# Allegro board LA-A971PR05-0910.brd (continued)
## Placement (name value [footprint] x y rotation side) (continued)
NOREF#24  -  []  129.2 19.65 0 top
NOREF#25  -  []  103 83.87 0 top
NOREF#26  -  []  103 61.73 0 top
NOREF#27  -  []  146.65 4.94 0 top
NOREF#28  -  []  227.2 108.55 180 bottom
NOREF#29  -  []  93.42 48.56 180 bottom
NOREF#30  -  []  40.82 35.98 180 bottom
NOREF#31  -  []  24.75 12.35 180 bottom
NOREF#32  -  []  24.34 8.13 180 bottom
PBATT1  LLTOP_ALLTOP C144LS-109A9-L 9P BATT P2  [ALLTO_C144LS-109A9-L_9P-T]  170.2 2.3 180 bottom
PC1  1U_0603_10V4Z  [C_0603]  225.71 96.8 270 top
PC3  2200P_0402_50V7K~D  [C_0402]  173.28 7.48 270 top
PC4  1500P_0402_50V7K  [C_0402]  157.02 7.86 270 top
PC5  0.022U_0805_50V7K  [C_0805]  81.75 84.43 0 top
PC9  1000P_0603_50V7K  [C_0603]  93.27 90.72 0 top
PC10  10U_0805_25V6K  [C_0805]  81.08 73.91 270 top
PC11  0.1U_0603_25V7K  [C_0603]  81.78 82.46 270 top
PC100  4.7U_0603_10V6K  [C_0603]  200.46 44.87 90 top
PC101  10U_0805_25V6K  [C_0805]  200.71 55.77 90 top
PC102  10U_0805_25V6K  [C_0805]  202.44 55.77 90 top
PC105  2200P_0402_50V7K  [C_0402]  203.73 56.48 90 top
PC106  0.1U_0402_25V6  [C_0402]  204.61 56.49 90 top
PC109  0.1U_0603_25V7K  [C_0603]  205.47 50.13 90 top
PC110  0.1U_0603_25V7K  [C_0603]  195.49 49.83 0 top
PC111  680P_0603_50V7K  [C_0603]  204.46 63.6 180 top
PC113  150U_D_6.3VM_R15M  [C_V]  211.89 62.08 90 bottom
PC114  680P_0603_50V7K  [C_0603]  200.46 63.41 0 top
PC115  150U_D_6.3VM_R15M  [C_V]  196.58 68.24 0 bottom
PC117  0.1U_0603_25V7K  [C_0603]  201.41 53.44 0 top
PC118  4.7U_0603_10V6K  [C_0603]  200.27 53.44 180 top
PC119  1U_0603_10V6K  [C_0603]  196.82 47.54 180 top
PC200  10U_0805_25V6K  [C_0805]  192.68 7.82 0 top
PC201  10U_0805_25V6K  [C_0805]  192.68 9.54 0 top
PC203  2200P_0402_50V7K  [C_0402]  193.61 6.49 0 top
PC204  0.22U_0603_16V7K  [C_0603]  190.87 9.05 180 top
PC205  22U_0805_6.3V6M  [C_0805]  182.74 6.83 180 top
PC206  0.1U_0402_25V6  [C_0402]  192.77 6.49 180 top
PC207  220U_D2_2VY_R17M  [C_D2]  204.33 13.14 270 bottom
PC208  680P_0603_50V7K  [C_0603]  201.47 7.91 180 top
PC209  1U_0603_10V6K  [C_0603]  190.88 5.44 180 top
PC211  1U_0603_10V6K  [C_0603]  189.48 2.97 0 top
PC212  0.033U_0402_16V7K  [C_0402]  183.19 5.5 180 top
PC213  100P_0402_50V8J  [C_0402]  182.74 3.7 90 top
PC214  .1U_0402_16V7K  [C_0402]  180.96 4.61 180 top
PC215  .1U_0402_16V7K  [C_0402]  186.4 3.29 270 top
PC300  2200P_0402_50V7K  [C_0402]  192.76 58.9 0 bottom
PC301  680P_0603_50V7K  [C_0603]  191.5 61.89 270 top
PC302  0.1U_0603_25V7K  [C_0603]  189.6 58.14 0 top
PC303  10U_0805_25V6K  [C_0805]  193.28 59.96 90 bottom
PC304  330P_0402_50V7K  [C_0402]  187.31 57.7 180 bottom
PC305  47U_0805_6.3V6M  [C_0805]  187.61 69.63 180 top
PC306  47U_0805_6.3V6M  [C_0805]  187.61 67.91 180 top
PC307  22U_0805_6.3VAM  [C_0805]  187.54 65.01 180 bottom
PC308  22U_0805_6.3VAM  [C_0805]  187.54 66.72 180 bottom
PC309  4.7U_0603_6.3V6K  [C_0603]  187.44 57.82 180 top
PC310  4.7U_0603_6.3V6K  [C_0603]  188.86 56.68 0 bottom
PC311  0.1U_0402_25V6  [C_0402]  190.32 57.72 180 bottom
PC400  1U_0402_6.3V6K  [C_0402]  95.01 95.47 180 bottom
PC401  4.7U_0805_6.3V6K  [C_0805]  95.72 92.75 0 bottom
PC402  .1U_0402_16V7K  [C_0402]  94.09 97.31 90 bottom
PC403  0.01U_0402_25V7K  [C_0402]  104.27 95.33 90 bottom
PC404  22U_0805_6.3V6M  [C_0805]  100.28 92.75 180 bottom
PC500  4700P_0603_50V7K  [C_0603]  90.09 68.36 90 top
PC501  .1U_0402_16V7K  [C_0402]  91.17 69.82 270 top
PC502  0.068U_0402_16V7K  [C_0402]  94.55 71.86 180 top
PC503  1000P_0402_50V7K  [C_0402]  77.81 66.38 0 bottom
PC504  0.1U_0402_25V6  [C_0402]  77.89 68.94 0 bottom
PC505  1U_0603_10V6K  [C_0603]  84.3 76.63 0 top
PC506  100P_0402_50V8J  [C_0402]  94.54 76.63 180 top
PC507  0.33U_0603_10V7K  [C_0603]  90.98 74.9 90 bottom
PC508  680P_0603_50V7K  [C_0603]  82.59 60.69 90 bottom
PC509  1U_0603_10V7K  [C_0603]  87.17 67.6 180 bottom
PC510  1U_0603_10V7K  [C_0603]  89.78 74.9 90 bottom
PC511  0.1U_0402_25V6  [C_0402]  86.14 80.56 0 top
PC512  1500P_0402_50V7K  [C_0402]  93.64 79.31 270 top
PC513  0.068U_0402_16V7K  [C_0402]  94.55 70.9 180 top
PC514  47P_0402_50V8J  [C_0402]  88.4 79.73 0 top
PC515  10U_0805_25V6K  [C_0805]  79.15 62.9 0 top
PC516  10U_0805_25V6K  [C_0805]  79.15 62.9 0 bottom
PC517  10U_0805_25V6K  [C_0805]  79.15 61.12 0 bottom
PC518  10U_0805_25V6K  [C_0805]  79.15 61.12 0 top
PC519  100U_D_20VM_R55M  [C_D]  80.55 57.58 0 bottom
PC520  2200P_0402_50V7K  [C_0402]  79.16 64.24 0 top
PC521  0.1U_0402_25V6  [C_0402]  79.17 65.13 0 top
PC700  0.1U_0603_25V7K  [C_0603]  48.44 24.36 270 top
PC701  1U_0603_25V6K  [C_0603]  53.2 9.37 90 bottom
PC702  0.1U_0402_25V6  [C_0402]  52.69 12.1 0 top
PC703  0.1U_0402_25V6  [C_0402]  54.23 10.45 270 bottom
PC704  10U_0805_25V6K  [C_0805]  81.09 12.96 90 top
PC705  10U_0805_25V6K  [C_0805]  77.53 12.96 90 top
PC706  10U_0805_25V6K  [C_0805]  79.35 12.96 90 bottom
PC707  10U_0805_25V6K  [C_0805]  77.53 12.96 90 bottom
PC708  22U_0805_25V6M  [C_0805]  81.09 12.96 90 bottom
PC709  10U_0805_25V6K  [C_0805]  54.95 12.15 0 top
PC710  1U_0603_10V6K  [C_0603]  57.01 7.09 0 top
PC711  0.1U_0402_25V6  [C_0402]  52.13 10.64 270 bottom
PC712  0.047U_0603_25V7K~D  [C_0603]  57.29 10.64 180 top
PC713  2200P_0402_50V7K  [C_0402]  61.4 14.74 0 bottom
PC714  22U_0805_25V6M  [C_0805]  59.22 10.62 0 top
PC715  22U_0805_25V6M  [C_0805]  60.68 14.83 0 top
PC716  22U_0805_25V6M  [C_0805]  59.08 10.39 0 bottom
PC717  22U_0805_25V6M  [C_0805]  60.69 13.09 0 top
PC718  100P_0402_50V8J  [C_0402]  50.36 9.72 90 bottom
PC719  100P_0402_50V8J  [C_0402]  51.18 8.71 180 bottom
PC721  1000P_0603_50V7K  [C_0603]  69.18 11.23 270 top
PC722  0.1U_0603_25V7K  [C_0603]  82.87 13.11 90 top
PC723  10U_0805_25V6K  [C_0805]  84.58 12.96 90 top
PC724  10U_0805_25V6K  [C_0805]  82.87 12.96 90 bottom
PC725  10U_0805_25V6K  [C_0805]  84.58 12.96 90 bottom
PC726  0.1U_0402_25V6  [C_0402]  52.88 6.69 270 bottom
PC727  0.1U_0402_25V6  [C_0402]  53.87 4.32 180 top
PC728  0.1U_0402_25V6  [C_0402]  51.99 5.78 90 bottom
PC729  1U_0603_25V6K  [C_0603]  55.22 5.93 180 bottom
PC732  0.1U_0402_25V6  [C_0402]  61.4 13.83 0 bottom
PC737  100P_0402_50V8J  [C_0402]  46.79 7.32 90 top
PC741  100P_0402_50V8J  [C_0402]  47.67 5.51 90 top
PC805  0.1U_0402_10V7K  [C_0402]  30.85 7.2 90 top
PC807  0.47U_0805_25V6K  [C_0805]  107.3 12.06 270 bottom
PC809  1500P_0402_50V7K  [C_0402]  17.82 40.51 0 top
PC810  0.1U_0402_10V7K  [C_0402]  15.51 38.91 0 top
PC813  0.1U_0603_50V4Z  [C_0603]  23.35 22.88 180 top
PC815  0.1U_0603_25V7K  [C_0603]  23.35 21.61 180 top
PC816  0.047U_0603_25V7M  [C_0603]  26.12 15.64 270 top
PC817  0.1U_0402_25V4Z~D  [C_0402]  27.15 15.67 270 top
PC900  22U_0805_6.3V6M  [C_0805]  106.14 66.44 90 bottom
PC901  22U_0805_6.3V6M  [C_0805]  104.4 66.44 90 bottom
PC902  22U_0805_6.3V6M  [C_0805]  102.68 66.45 90 bottom
PC903  22U_0805_6.3V6M  [C_0805]  106.11 69.81 90 bottom
PC904  22U_0805_6.3V6M  [C_0805]  104.4 69.81 90 bottom
PC913  22U_0805_6.3V6M  [C_0805]  105.98 73.14 90 bottom
PC914  22U_0805_6.3V6M  [C_0805]  104.24 73.13 90 bottom
PC915  2.2U_0805_10V6K  [C_0805]  102.68 69.81 90 bottom
PC916  2.2U_0805_10V6K  [C_0805]  100.95 66.45 90 bottom
PC917  22U_0805_6.3V6M  [C_0805]  102.51 73.13 90 bottom
PC966  220U 2.5V Y D2 ESR9M H1.9 SX  [C_D2]  96.55 82 90 bottom
PD1  -  [TVNST52302AB0_SOT523-3]  166.87 6.58 180 top
PD2  -  [TVNST52302AB0_SOT523-3]  164.83 7.98 0 top
PD3  BAS40CW SOT-323  [BAS40-05W_SC70-3]  226.82 96.11 90 top
PD4  SDMK0340L-7-F_SOD323-2~D  [RB751V-40_SOD323-2]  162.99 8.85 270 top
PD5  -  [AZC199-02SPR7G_SOT23-3]  75.9 95.69 180 top
PD702  SDMK0340L-7-F_SOD323-2~D  [SDMK0340L-7-F_SOD323-2]  59.61 4.99 180 bottom
PD704  SDMK0340L-7-F_SOD323-2~D  [SDMK0340L-7-F_SOD323-2]  102.89 7.35 180 bottom
PD705  SDMK0340L-7-F_SOD323-2~D  [SDMK0340L-7-F_SOD323-2]  102.89 9.09 180 bottom
PD800  -  [PDS5100H-13_POWERDI5-3]  87.44 7.25 0 bottom
PD808  -  [PDS5100H-13_POWERDI5-3]  105.32 9.37 180 top
PD813  SDMK0340L-7-F_SOD323-2~D  [SDMK0340L-7-F_SOD323-2]  23.04 38.77 270 top
PD815  -  [BAT54CW_SOT323-3]  35.75 20.57 180 top
PD817  -  [BAT54CW_SOT323-3]  26.02 35.5 90 top
PH500  100K_0402_1%_NCP15WF104F03RC  [R_0402]  84.52 69.63 180 bottom
PH501  10K_0402_1%_TSM0A103F34D1RZ  [R_0402]  92.48 66.15 0 top
PJP1  PAD-OPEN 1x3m  [JUMP_43X118]  91.58 81.51 0 bottom
PJP6  PAD-OPEN1x2m  [JUMP_43X79]  254.28 44.87 180 top
PJP9  PAD-OPEN1X2m  [JUMP_43X79]  251.6 26.31 90 top
PJP10  PAD-OPEN1x1m  [JUMP_43X39]  254.61 25.47 90 top
PJP11  PAD-OPEN1x1m  [JUMP_43X39]  193.85 52.95 270 top
PJP12  PAD-OPEN1x1m  [JUMP_43X39]  197.47 43.17 270 top
PJP13  PAD-OPEN1x1m  [JUMP_43X39]  209.28 49.45 270 bottom
PJP14  PAD-OPEN1x1m  [JUMP_43X39]  237.61 49.73 180 top
PJP15  PAD-OPEN1x1m  [JUMP_43X39]  252.84 59.93 180 top
PJP16  PAD-OPEN1x1m  [JUMP_43X39]  214.16 14.01 180 top
PJP19  PAD-OPEN1x1m  [JUMP_43X39]  45.39 29.96 270 top
PJP20  PAD-OPEN1x1m  [JUMP_43X39]  45.45 23.8 270 top
PJP21  PAD-OPEN1x3m  [JUMP_43X118]  208.29 75.59 270 top
PJP22  PAD-OPEN1x3m  [JUMP_43X118]  210.38 66.71 0 top
PJP23  PAD-OPEN1x1m  [JUMP_43X39]  132.89 90.03 270 top
PJP24  PAD-OPEN1x1m  [JUMP_43X39]  209.81 83.5 90 bottom
PJP25  PAD-OPEN1x1m  [JUMP_43X39]  209.87 78.51 270 bottom
PJP26  PAD-OPEN1x1m  [JUMP_43X39]  253.21 11.28 0 top
PJP27  PAD-OPEN1x1m  [JUMP_43X39]  207.63 78.41 270 bottom
PJP28  PAD-OPEN1x1m  [JUMP_43X39]  207.59 84.42 270 bottom
PJP29  PAD-OPEN1x1m  [JUMP_43X39]  179.57 55.97 90 top
PJP32  PAD-OPEN1x1m  [JUMP_43X39]  211.06 42.57 90 bottom
PJP36  PAD-OPEN1x1m  [JUMP_43X39]  147.04 91.49 180 top
PJP41  PAD-OPEN1x1m  [JUMP_43X39]  211.51 49.45 270 bottom
PJP42  PAD-OPEN1x1m  [JUMP_43X39]  213.28 42.57 90 bottom
PJP51  PAD-OPEN1x1m  [JUMP_43X39]  146.1 89.26 0 top
PJP100  PAD-OPEN 1x3m  [JUMP_43X118]  211.23 53.53 90 bottom
PJP101  PAD-OPEN 1x3m  [JUMP_43X118]  199.44 67.12 90 top
PJP102  PAD-OPEN 1x3m  [JUMP_43X118]  206.93 67.31 90 bottom
PJP200  PAD-OPEN 1x2m~D  [JUMP_43X79]  193.79 4.04 180 top
PJP201  PAD-OPEN1x1m  [JUMP_43X39]  189.85 12.93 0 top
PJP202  PAD-OPEN1x1m  [JUMP_43X39]  182.37 8.8 180 top
PJP203  JUMP_1x3m  [JUMP_43X118]  199.83 13.89 90 top
PJP204  JUMP_1x3m  [JUMP_43X118]  202.8 18.95 180 top
PJP300  PAD-OPEN 1x2m~D  [JUMP_43X79]  186.23 62.75 270 bottom
PJP302  PAD-OPEN 1x2m~D  [JUMP_43X79]  192.65 56.19 90 bottom
PJP400  PAD-OPEN1x1m  [JUMP_43X39]  94.03 92.95 90 bottom
PJP401  PAD-OPEN1x1m  [JUMP_43X39]  101.57 92.49 0 bottom
PJP500  PAD-OPEN 4x4m  [JUMP_43X118]  74.81 57.38 0 bottom
PJP700  PAD-OPEN 1x2m~D  [JUMP_43X79-NPM]  57.68 13.75 0 bottom
PJP701  PAD-OPEN1x1m  [JUMP_43X39]  54.47 8.17 270 bottom
PJPDC1  ACES_50299-0050N-001  [ACES_50299-0050N-001_5P]  91.35 92.8 270 bottom
PL1  FBMJ4516HS720NT_2P~D  [TAIYO_FBMJ4516HS720NT_2P]  169.02 7.08 90 top
PL2  FBMJ4516HS720NT_2P~D  [TAIYO_FBMJ4516HS720NT_2P]  171.31 7.08 90 top
PL3  BLM15AG102SN1D_2P  [MURAT_BLM15AG102SN1D_2P]  75.81 91.87 180 top
PL4  FBMJ4516HS720NT_2P  [TAIYO_FBMJ4516HS720NT_2P]  86.29 81.7 180 bottom
PL100  1UH +-20% 6.6A  [L_5X5X3_M_2P-NPM]  211.23 52.03 90 bottom
PL101  2.2UH_7.8A_20%  [PANAS_ETQP3W2R2WFN_2P]  205.6 63.9 90 bottom
PL102  3.3UH_6.3A_20%  [PANAS_ETQP3W2R2WFN_2P]  198.11 57.91 270 bottom
PL200  1UH_11A_20%  [PANAS_ETQP3W2R2WFN_2P]  200.05 10.39 0 bottom
PL301  0.68UH +-20% 7.9A  [L_5X5X3_M_2P]  191.76 64.73 90 bottom
PL500  0.15UH_PCME064T-R15MS0R667_36A_20%  [PANAS_ETQP4LR15AFM_4P]  96.42 62.66 180 bottom
PL501  FBMA-L11-453215800LMA90T_2P  [KC_FBMA-L1_2P-NPM]  73.46 57.38 0 bottom
PL700  1UH_PCMB042T-1R0MS_4.5A_20%  [CYNTE_PCMB042T-1R0MS_2P]  60.02 13.5 180 bottom
PL701  3.3UH +-20% PIMB104T 10A  [TOKO_FDVE1040-H-3R3M-P3_2P]  73.78 10.43 180 bottom
PQ1  -  [DMG2301U-7_SOT23-3]  160.86 8.04 90 top
PQ2  -  [FDV301N-G_SOT23-3]  78.18 87.86 90 top
PQ3  MMST3904-7-F_SOT323~D  [MMST3904-7-F_SOT323-3]  72.44 87.16 90 top
PQ4  -  [FDMC6679AZ_MLP8-5]  82.07 79.99 0 bottom
PQ6  DCX124EK-7-F PNP/NPN_SC74-6~D  [IMD2AT-108_SC74-6]  82.99 87.98 90 top
PQ100  -  [SIS412DN-T1-GE3_POWERPAK8-5]  208.05 58.18 180 top
PQ101  -  [SIS412DN-T1-GE3_POWERPAK8-5]  198.91 58.24 180 top
PQ102  -  [SI7716ADN-T1-GE3_POWERPAK8-5]  203.97 61.99 270 top
PQ103  -  [SI7716ADN-T1-GE3_POWERPAK8-5]  201 59.75 90 top
PQ200  -  [SIS412DN-T1-GE3_POWERPAK8-5]  195.1 11.3 90 top
PQ201  -  [SI7716ADN-T1-GE3_POWERPAK8-5]  196.61 8.95 0 top
PQ700  V30415-T1-GE3 1P POWERPAK1212-8  [SI7121DN-T1-GE3_POWERPAK8-5]  80.78 73.72 90 bottom
PQ701  -  [NTR4502PT1G_SOT23-3]  49.82 17.26 270 top
PQ702  -  [NTR4502PT1G_SOT23-3]  49.82 21.26 270 top
PQ703  SI3993CDV-T1-GE3_TSOP6  [NTGD4161PT1G_TSOP6]  54.18 19.72 270 top
PQ704  -  [AON6970_DFN5X6D-8-7]  61.35 8.61 270 top
PQ712  -  [DMN65D8LW-7_SOT323-3]  22.28 29.6 90 top
PQ800  -  [SI4835DDY-T1-GE3_SO8]  86.63 10.3 90 bottom
PQ806  -  [DMN65D8LDW-7_SOT363-6]  34.17 11.57 180 top
PQ810  -  [FDS6679AZ-G_SO8]  104.77 14.52 270 bottom
PQ813  -  [DMN65D8LDW-7_SOT363-6]  27.53 29.53 0 top
PQ814  -  [NTR4502PT1G_SOT23-3]  22.21 33.2 270 top
PQ815  -  [FDS6679AZ-G_SO8]  93.78 11.03 0 bottom
PQ816  -  [DMN65D8LW-7_SOT323-3]  18.92 36.99 90 top
PQ817  -  [DMN65D8LDW-7_SOT363-6]  12.2 36.19 0 top
PQ826  -  [FDMC6679AZ_MLP8-5]  94.92 12.91 90 bottom
PQ829  DMG2301U-7 1P SOT23-3  [SI2301CDS-T1-GE3_SOT23-3]  35.55 24.97 0 top
PQ832  -  [DMN65D8LW-7_SOT323-3]  33.39 29.69 90 top
PR1  1K_0402_5%  [R_0402]  229.64 96.62 270 top
PR2  100K_0402_5%  [R_0402]  162.6 10.13 0 top
PR6  0_0402_5%  [R0402_0OHM]  157.02 9.64 270 top
PR7  0_0402_5%  [R_0402]  76.07 84.49 180 top
PR8  2.2K_0402_5%  [R_0402]  74.22 84.51 270 top
PR9  33_0402_5%  [R_0402]  75.18 85.4 180 top
PR10  100K_0402_1%  [R_0402]  75.16 83.6 0 top
PR11  10K_0402_1%  [R_0402]  73.52 86.96 90 top
PR12  15K_0402_1%  [R_0402]  69.89 84.81 0 top
PR13  10K_0402_5%  [R_0402]  74.41 87.87 270 top
PR14  1M_0402_5%  [R_0402]  80.7 82.07 90 top
PR15  100K_0402_5%  [R_0402]  82.41 73.52 270 top
PR16  4.7K_0805_5%  [R_0805]  83.3 82.55 270 top
PR17  10K_0402_5%  [R_0402]  80.26 84.75 180 top
PR18  1M_0402_5%  [R_0402]  80.26 83.86 180 top
PR100  6.49K_0402_1%  [R_0402]  202.48 45.44 90 top
PR101  15K_0402_1%  [R_0402]  199.43 46.35 270 top
PR102  10K_0402_1%  [R_0402]  203.36 45.44 90 top
PR103  0_0402_5%  [R0402_0OHM]  201.54 45.43 90 top
PR104  10K_0402_1%  [R_0402]  198.54 46.35 270 top
PR105  20K_0402_1%  [R_0402]  204.25 45.44 90 top
PR106  16.9K_0402_1%  [R_0402]  197.65 45.44 90 top
PR107  100K_0402_1%  [R_0402]  205.16 48.69 270 top
PR108  0_0402_5%  [R0402_0OHM]  204.25 47.78 90 top
PR109  2.2_0603_5%  [R_0603]  196.89 51.1 180 top
PR110  2.2_0603_5%  [R_0603]  205.71 52.62 180 top
PR111  4.7_1206_5%  [R_1206]  208.33 63.86 180 top
PR112  4.7_1206_5%  [R_1206]  196.58 63.66 0 top
PR113  0_0402_5%  [R0402_0OHM]  195.68 46.46 0 top
PR114  200_0402_1%  [R_0402]  196.58 48.69 180 top
PR200  2.2_0603_5%  [R_0603]  189.85 10.39 180 top
PR201  19.6K_0402_1%  [R_0402]  190.42 6.51 180 top
PR202  5.1_0603_5%  [R_0603]  188.34 2.31 90 top
PR203  4.7_1206_5%  [R_1206]  200.39 11.85 270 top
PR204  0_0603_5%  [R_0603]  189.48 4.21 0 top
PR205  8.06K_0402_1%  [R_0402]  181.85 3.7 90 top
PR206  768K_0402_1%  [R_0402]  187.29 2.37 90 top
PR207  0_0402_5%  [R0402_0OHM]  185.47 2.37 90 top
PR209  10K_0402_1%  [R_0402]  180.98 3.72 180 top
PR210  0_0402_5%  [R0402_0OHM]  184.58 2.37 90 top
PR303  1M_0402_1%  [R_0402]  187.39 59.08 180 bottom
PR305  4.7_1206_5%  [R_1206]  188.96 63.35 0 top
PR306  0_0402_5%  [R_0402]  186.54 59.09 0 top
PR307  7.5K_0402_1%  [R_0402]  187.31 56.81 180 bottom
PR308  0_0402_5%  [R_0402]  187.45 59.98 180 top
PR309  1K_0402_5%  [R_0402]  185.52 57.71 270 bottom
PR310  10K_0402_1%  [R_0402]  186.63 55.94 180 bottom
PR312  0_0603_5%  [R_0603]  190.23 59.22 90 top
PR313  0_0402_5%  [R0402_0OHM]  186.16 61.81 0 top
PR315  100K_0402_1%  [R_0402]  186.16 60.92 0 top
PR400  100K_0402_5%  [R_0402]  94.1 96.42 0 bottom
PR401  47K_0402_5%  [R_0402]  94.98 97.31 90 bottom
PR402  8.66K_0402_1%  [R_0402]  103.38 95.33 90 bottom
PR403  10K_0402_1%  [R_0402]  103.38 97.17 90 bottom
PR500  75_0402_1%  [R_0402]  92.06 69.82 270 top
PR501  316K_0402_1%  [R_0402]  89.01 68.91 90 top
PR502  75_0402_1%  [R_0402]  88.06 69.82 270 top
PR503  681K_0402_1%  [R_0402]  87.17 69.82 270 top
PR504  36.5K_0402_1%  [R_0402]  86.28 69.82 270 top
PR505  10K_0402_5%  [R_0402]  90.59 72.57 270 bottom
PR506  39K_0402_1%  [R_0402]  89.7 72.57 270 bottom
PR507  150K_0402_1%  [R_0402]  88.81 72.57 270 bottom
PR508  100K_0402_1%  [R_0402]  87.92 72.57 270 bottom
PR509  20K_0402_1%  [R_0402]  87.03 72.57 270 bottom
PR510  39K_0402_5%~N  [R_0402]  91.48 72.57 270 bottom
PR511  10K_0402_5%  [R_0402]  92.95 68.87 90 top
PR512  2.15K_0402_1%  [R_0402]  91.6 65.27 270 top
PR513  75_0402_1%  [R_0402]  85.14 72.56 180 top
PR514  20K_0402_1%  [R_0402]  92.49 65.27 270 top
PR515  3.01K_0402_1%  [R_0402]  93.38 65.27 270 top
PR516  1.91K_0402_1%  [R_0402]  85.14 74.34 180 top
PR517  2.2_0603_5%  [R_0603]  79.03 67.8 180 bottom
PR518  2M_0402_1%  [R_0402]  89.05 69.1 0 bottom
PR519  1_0603_5%  [R_0603]  84.3 75.42 0 top
PR520  0_0402_5%  [R0402_0OHM]  84.23 71.67 0 top
PR521  4.22K_0402_1%  [R_0402]  92.68 77.63 90 top
PR522  4.7_1206_5%  [R_1206]  84.24 63.35 270 bottom
PR523  10K_0402_5%  [R_0402]  94.54 77.52 180 top
PR524  2M_0402_1%  [R_0402]  89.97 69.98 180 bottom
PR525  27K_0402_1%  [R_0402]  89.97 68.21 180 bottom
PR526  10_0603_1%  [R_0603]  90.22 78.84 0 top
PR527  54.9_0402_1%  [R_0402]  87.05 79.68 270 top
PR528  75_0402_1%  [R_0402]  86.16 79.68 270 top
PR529  110_0402_1%  [R_0402]  85.03 78.02 180 top
PR531  0_0402_5%  [R0402_0OHM]  94.54 75.61 180 top
PR532  0_0402_5%  [R0402_0OHM]  94.54 74.72 180 top
PR534  0_0402_5%  [R0402_0OHM]  89 78.86 270 top
PR535  4.75K_0402_1%  [R_0402]  94.53 78.39 90 top
PR536  0_0402_5%  [R0402_0OHM]  84.23 70.78 0 top
PR539  0_0402_5%  [R0402_0OHM]  85.14 73.45 180 top
PR700  0_0402_5%  [R0402_0OHM]  79.57 75.73 180 bottom
PR701  0.01_1206_1%  [R_1206_4P-D]  54.83 14.41 180 bottom
PR702  0_0402_5%  [R0402_0OHM]  47.36 24.12 270 top
PR703  100_0402_1%  [R_0402]  53.95 14.85 180 top
PR704  0_0402_5%  [R0402_0OHM]  53.06 13.06 90 top
PR705  0_0402_5%  [R0402_0OHM]  53.95 13.06 90 top
PR706  100K_0402_1%  [R_0402]  52.12 23.77 90 top
PR707  100K_0402_1%  [R_0402]  50.33 23.79 0 top
PR708  10_1206_5%  [R_1206]  57.35 7.97 90 bottom
PR709  0_0402_5%  [R0402_0OHM]  50.33 24.68 0 top
PR710  34K_0402_1%  [R_0402]  51.55 12.78 270 top
PR711  6.49K_0402_1%  [R_0402]  51.25 10.64 270 bottom
PR712  2.2_0603_5%  [R_0603]  57.14 8.17 90 top
PR713  100K_0402_1%  [R_0402]  48.57 3.52 90 top
PR714  0_0402_5%  [R0402_0OHM]  50.67 12.8 270 top
PR715  154K_0402_1%  [R_0402]  49.9 5.78 90 bottom
PR716  0_0402_5%  [R0402_0OHM]  49.79 12.8 270 top
PR717  0_0402_5%  [R0402_0OHM]  47.42 9.6 0 top
PR718  0_0402_5%  [R0402_0OHM]  47.42 11.38 0 top
PR720  0_0402_5%  [R0402_0OHM]  47.42 10.49 0 top
PR721  0.01_1206_1%  [R_1206_4P-D]  83.26 11.21 180 bottom
PR722  4.02K_0402_1%  [R_0402]  52.11 4.39 270 top
PR723  10_0603_1%  [R_0603]  54.18 4.71 0 bottom
PR725  1K_0402_1%  [R_0402]  51.23 3.49 90 top
PR726  4.7_1206_5%  [R_1206]  67.88 10.65 180 top
PR728  0_0402_5%  [R0402_0OHM]  49.44 4.33 0 top
PR729  154K_0402_1%  [R_0402]  50.79 5.78 90 bottom
PR737  649K_0402_1%  [R_0402]  45.91 8.23 270 top
PR738  3M_0402_5%  [R_0402]  48.59 7.24 270 top
PR740  10K_0402_1%  [R_0402]  46.78 6.42 270 top
PR743  0_0402_5%  [R0402_0OHM]  45.84 6.45 270 top
PR745  100K_0402_1%  [R_0402]  47.68 7.32 90 top
PR788  20K_0402_1%  [R_0402]  51.18 7.82 180 bottom
PR799  10K_0402_1%  [R_0402]  56.05 4.44 90 top
PR810  100K_0402_5%  [R_0402]  29.36 11.53 270 top
PR811  0_0402_5%  [R0402_0OHM]  106.85 9.31 0 bottom
PR812  0_0402_5%  [R0402_0OHM]  30.02 9.17 0 top
PR813  100K_0402_5%  [R_0402]  27.98 7.85 270 top
PR814  330K_0402_5%  [R_0402]  28.38 27.98 180 top
PR815  100K_0402_5%  [R_0402]  27.05 7.85 270 top
PR816  0_0402_5%  [R_0402]  26.14 7.85 270 top
PR818  100K_0402_5%  [R_0402]  18.73 39.62 180 top
PR819  100K_0402_5%  [R_0402]  12.2 39.17 0 top
PR822  10K_0402_5%  [R_0402]  19.66 39.64 270 top
PR826  100K_0402_5%  [R_0402]  26.08 32.73 0 top
PR827  100K_0402_5%  [R_0402]  26.08 33.62 0 top
PR828  10K_0402_5%  [R_0402]  35.5 31.47 180 top
PR829  100K_0402_5%  [R_0402]  29.9 30.78 270 top
PR830  100K_0402_5%  [R_0402]  33.01 27.77 90 top
PR831  100_0603_1%  [R_0603]  26.15 27.05 270 top
PR832  100_0603_1%  [R_0603]  27.36 25.65 90 top
PR835  47_0805_5%~D  [R_0805]  21.62 24.49 0 top
PR838  100_0603_1%  [R_0603]  30.38 25.48 90 top
PR842  0_0402_5%  [R0402_0OHM]  22.51 20.56 0 top
PR843  0_0402_5%  [R0402_0OHM]  33.18 23.65 0 top
PR844  10K_0402_5%  [R_0402]  36.13 19.6 180 top
PR845  0_0402_5%  [R0402_0OHM]  33.18 22.76 0 top
PR846  100K_0402_5%  [R_0402]  20.74 20.57 0 top
PR847  100_0603_1%  [R_0603]  21.98 19.52 0 top
PR848  0_0402_5%  [R0402_0OHM]  33.18 21.17 0 top
PR850  0_0402_5%  [R0402_0OHM]  33.18 19.39 0 top
PR851  0_0402_5%  [R0402_0OHM]  22.51 18.48 0 top
PR853  0_0402_5%  [R0402_0OHM]  28.77 33.62 180 top
PR854  0_0402_5%  [R0402_0OHM]  33.2 18.44 0 top
PR855  0_0402_5%  [R0402_0OHM]  22.51 17.55 0 top
PR857  0_0402_5%  [R0402_0OHM]  30.16 15.66 270 top
PR858  1M_0402_5%  [R_0402]  34.09 20.28 180 top
PR859  0_0402_5%  [R0402_0OHM]  31.03 15.66 270 top
PR860  100_0603_1%  [R_0603]  28.23 15.66 270 top
PR863  0_0402_5%  [R_0402]  33.2 17.49 0 top
PR864  100K_0402_5%  [R_0402]  22.42 16.67 180 top
PR874  1M_0402_5%  [R_0402]  29.27 15.66 270 top
PR895  0_0402_5%  [R0402_0OHM]  32.12 28.69 270 top
PRP2  100_0804_8P4R_5%  [RP_0804_8P4R]  166.6 10.46 270 top
PT1  PAD~D  [TPC12]  45.07 10.71 0 top
PT2  PAD~D  [TPC12]  45.33 9.37 0 top
PU1  TS5A63157DCKR_SC70-6~D  [TS5A63157DCKR_SC70-6]  71.93 83.07 0 top
PU100  -  [TPS51285BRUKR_QFN20_3X3]  199.82 48.41 0 top
PU200  -  [RT8207MZQW_WQFN20_3X3]  184.94 7.44 270 top
PU300  -  [SYX198DQNC_QFN10_3X3]  188.9 61.8 270 bottom
PU400  -  [APL5930KAI-TRG_SO8]  101.77 98.2 270 bottom
PU500  TPS51624RSM_QFN32_4X4  [TPS51622RSM_QFN32_4X4]  87.51 75.29 270 top
PU501  -  [CSD97374CQ4M_SON8_3P5X4P5]  84.15 68.26 270 bottom
PU700  BQ24777RUYR_WQFN28_4x4  [BQ24715URUYR_WQFN28_4X4]  53.7 10 270 top
PU800  CD3301BRHHR_QFN36_6X6~D  [CD3301RHHR_QFN36_6X6]  25.46 22.85 270 top
PU804  TC7SH08FU_SSOP5~D  [TC7SH08FU_SSOP5]  30.4 10.26 0 top
PU806  TC7SH08FU_SSOP5~D  [TC7SH08FU_SSOP5]  14.82 37.59 270 top
QA1  -  [L2N7002WT1G_SC-70-3]  267.13 30.71 0 top
QA2  -  [DMN66D0LDW-7_SOT363-6]  265.37 45.25 180 top
QA3  -  [DMN66D0LDW-7_SOT363-6]  269.15 28.81 0 top
QC1  -  [DMN66D0LDW-7_SOT363-6]  173.02 58.51 90 top
QD1  -  [L2N7002WT1G_SC-70-3]  123.05 32.8 0 top
QE2  -  [DMN66D0LDW-7_SOT363-6]  234.41 67.78 90 top
QE3  MMBT3904WT1G_SC70-3~D  [MMBT3904WT1G_SC70-3]  131.38 74.28 90 top
QE4  -  [MMBT3904WT1G_SC70-3]  231.88 58.94 90 top
QE5  MMBT3904WT1G_SC70-3~D  [MMBT3904WT1G_SC70-3]  52.13 27.55 90 top
QE6  MMBT3904WT1G_SC70-3~D  [MMBT3904WT1G_SC70-3]  93.46 57.38 90 top
QE7  MMBT3904WT1G_SC70-3~D  [MMBT3904WT1G_SC70-3]  222.72 19.36 90 top
QL1  -  [DMN66D0LDW-7_SOT363-6]  263.76 79.78 90 top
QL2  -  [DMN66D0LDW-7_SOT363-6]  261.81 78.61 270 top
QV1  -  [AO6405_TSOP6]  63.03 69.12 270 bottom
QV2  -  [L2N7002WT1G_SC-70-3]  63.29 63.16 90 bottom
QV7  -  [L2N7002WT1G_SC-70-3]  76.89 77.51 0 top
QV8  -  [LP2301ALT1G_SOT23-3]  72.8 80.3 270 top
QV9  -  [L2N7002WT1G_SC-70-3]  182.14 88.18 270 top
QV10  -  [L2N7002WT1G_SC-70-3]  186.36 73.74 0 top
QV501  -  [L2N7002WT1G_SC-70-3]  265.23 74.08 180 top
QV502  -  [L2N7002WT1G_SC-70-3]  265.67 72.17 90 top
QV700  -  [DMN66D0LDW-7_SOT363-6]  193.11 70.8 90 top
QZ1  -  [LP2301ALT1G_SOT23-3]  73.36 76.3 90 top
QZ2  -  [DMN66D0LDW-7_SOT363-6]  214.55 18.25 90 top
QZ3  -  [DMN66D0LDW-7_SOT363-6]  213.03 87.05 270 bottom
QZ4  -  [DDTA114EUA-7-F_SOT323-3]  208.37 86.44 90 bottom
QZ5  -  [DMN66D0LDW-7_SOT363-6]  203.63 94.08 0 top
QZ6  -  [SI3456DDV-T1-GE3_TSOP6]  148.09 96.37 180 top
QZ7  -  [DMN66D0LDW-7_SOT363-6]  264.1 81.52 180 bottom
QZ9  -  [DDTA114EUA-7-F_SOT323-3]  262.84 83.48 270 top
QZ10  -  [DMN66D0LDW-7_SOT363-6]  137.29 93.2 90 top
QZ11  -  [DMN66D0LDW-7_SOT363-6]  221.66 57.55 90 top
QZ12  -  [DDTA114EUA-7-F_SOT323-3]  207.9 89.08 90 bottom
QZ14  -  [DMN66D0LDW-7_SOT363-6]  212.58 89.78 270 bottom
R6  10_0402_5%  [R_0402]  134.35 97.13 180 bottom
R41  10_0402_5%  [R_0402]  135.2 97.14 0 bottom
R252  33_0402_5%  [R_0402]  115.86 96.18 90 bottom
R253  33_0402_5%  [R_0402]  116.75 96.18 90 bottom
R254  33_0402_5%  [R_0402]  118.21 104.97 270 top
R255  33_0402_5%  [R_0402]  117.64 96.18 90 bottom
R256  33_0402_5%  [R_0402]  119.1 104.97 270 top
R257  33_0402_5%  [R_0402]  118.53 96.18 90 bottom
R258  33_0402_5%  [R_0402]  121.77 104.97 270 top
R259  33_0402_5%  [R_0402]  114.97 96.18 90 bottom
R260  33_0402_5%  [R_0402]  116.44 104.97 270 top
R261  33_0402_5%  [R_0402]  117.32 104.97 270 top
R262  33_0402_5%  [R_0402]  119.99 104.97 270 top
R263  33_0402_5%  [R_0402]  119.42 96.18 90 bottom
R264  33_0402_5%  [R_0402]  120.88 104.97 270 top
R265  33_0402_5%  [R_0402]  120.31 96.18 90 bottom
R266  33_0402_5%  [R_0402]  121.2 96.18 90 bottom
R267  33_0402_5%  [R_0402]  122.66 104.97 270 top
R268  100K_0402_5%  [R_0402]  123.86 97.09 270 bottom
R271  100K_0402_5%  [R_0402]  132.49 105.16 270 top
R272  100K_0402_5%  [R_0402]  162.12 98.03 180 bottom
R273  10_0402_5%  [R_0402]  145.77 99.98 90 top
RA1  10K_0402_5%  [R_0402]  273.23 39.39 90 top
RA2  100K_0402_5%  [R_0402]  266.61 27.66 0 top
RA3  0_0603_5%  [R0603_0OHM]  253.16 38.58 0 top
RA4  0_0603_5%  [R0603_0OHM]  253.1 42.33 270 top
RA5  2.2K_0402_5%  [R_0402]  262.79 41.6 90 top
RA6  2.2K_0402_5%  [R_0402]  262.79 44.74 270 top
RA7  24.9_0402_1%  [R_0402]  269.67 37.93 90 top
RA8  24.9_0402_1%  [R_0402]  271.48 38.21 90 bottom
RA9  33_0402_5%  [R_0402]  262.62 26.95 90 top
RA12  1K_0402_5%  [R_0402]  264.47 28.37 270 top
RA13  1K_0402_5%  [R_0402]  265.42 28.37 270 top
RA14  33_0402_5%  [R_0402]  257.35 30.21 270 top
RA17  33_0402_5%  [R_0402]  260.78 30.09 270 top
RA18  10K_0402_5%  [R_0402]  255.5 30.58 0 top
RA21  100K_0402_5%  [R_0402]  266.75 45.07 270 top
RA24  4.7K_0402_5%  [R_0402]  270.75 38.85 270 top
RA25  4.7K_0402_5%  [R_0402]  272.39 39.13 270 bottom
RA26  100K_0402_5%  [R_0402]  270.26 31.85 180 top
RA27  200K_0402_5%  [R_0402]  267.45 32.75 270 top
RA28  100K_0402_5%  [R_0402]  268.4 32.75 270 top
RA29  100K_0402_5%  [R_0402]  268.9 27.66 0 top
RA30  22_0402_5%  [R_0402]  266.56 32.75 180 top
RA31  22_0402_5%  [R_0402]  270.08 33.71 180 top
RA32  33_0402_5%  [R_0402]  270.07 34.61 180 top
RA35  0_0402_5%  [R0402_0OHM]  252.83 36.18 270 top
RA36  0_0402_5%  [R0402_0OHM]  274.63 35.86 270 top
RA37  0_0402_5%  [R0402_0OHM]  259.91 47.24 90 top
RA38  100K_0402_5%  [R_0402]  269.34 32.8 0 top
RA39  0_0805_5%  [R0805_0OHM]  253.42 32.33 90 top
RA44  100K_0402_5%  [R_0402]  266.56 36.64 0 top
RA45  0_0402_5%  [R0402_0OHM]  266.57 38.75 0 top
RC1  330K_0402_5%  [R_0402]  150.99 55.52 90 bottom
RC2  1K_0402_5%  [R_0402]  148.48 54.66 180 top
RC4  0_0402_5%  [R0402_0OHM]  163.14 56.3 0 bottom
RC7  10M_0402_5%  [R_0402]  165.42 56.3 0 bottom
RC8  20K_0402_5%  [R_0402]  168.26 58.06 90 bottom
RC9  1M_0402_5%  [R_0402]  154.8 55.52 90 bottom
RC10  20K_0402_5%  [R_0402]  168.26 56.82 270 bottom
RC11  1K_0402_5%  [R_0402]  148.48 53.7 180 top
RC17  3.01K_0402_1%  [R_0402]  141.97 87.15 90 bottom
RC18  1K_0402_1%  [R_0402]  97.85 58.65 180 top
RC19  33_0402_5%  [R_0402]  147.43 55.52 90 bottom
RC20  33_0402_5%  [R_0402]  146.42 55.52 90 bottom
RC21  51_0402_5%  [R_0402]  107.94 67.67 0 bottom
RC22  33_0402_5%  [R_0402]  150.1 55.52 90 bottom
RC23  33_0402_5%  [R_0402]  148.32 55.52 90 bottom
RC25  1K_0402_5%  [R_0402]  110.1 90.6 270 bottom
RC26  0_0402_5%  [R0402_0OHM]  168.78 62.2 180 top
RC27  0_0402_5%  [R_0402]  168.78 61.19 180 top
RC29  1K_0402_5%  [R_0402]  171.31 74.19 90 bottom
RC30  0_0402_5%  [R0402_0OHM]  165.04 69.63 180 top
RC31  1K_0402_5%  [R_0402]  166.37 75.67 180 top
RC32  0_0402_5%  [R0402_0OHM]  165.04 68.74 180 top
RC33  499_0402_1%  [R_0402]  165.04 67.86 180 bottom
RC34  499_0402_1%  [R_0402]  165.04 68.74 180 bottom
RC35  0_0402_5%  [R0402_0OHM]  169.55 88.37 180 bottom
RC38  33_0402_5%  [R_0402]  167.06 82.83 90 bottom
RC50  0_0402_5%  [R0402_0OHM]  173.85 69.52 270 bottom
RC55  33_0402_5%  [R_0402]  170.42 75.11 270 bottom
RC61  33_0402_5%  [R_0402]  167.64 73.44 180 top
RC62  33_0402_5%  [R_0402]  167.06 80.92 90 bottom
RC63  1M_0402_5%  [R_0402]  136.65 88.05 180 bottom
RC65  0_0402_5%  [R0402_0OHM]  137.52 87.16 0 bottom
RC66  10K_0402_5%  [R_0402]  158.17 71.72 180 top
RC67  22_0402_5%  [R_0402]  143.02 52.18 270 top
RC68  10K_0402_5%  [R_0402]  155.93 76.31 180 bottom
RC69  3.01K_0402_1%  [R_0402]  134.86 87.15 90 bottom
RC70  22_0402_5%  [R_0402]  143.97 52.18 270 top
RC72  22_0402_5%  [R_0402]  140.86 52.18 270 top
RC74  22_0402_5%  [R_0402]  141.75 52.18 270 top
RC77  0_0402_5%  [R0402_0OHM]  166.8 81.67 270 top
RC78  330K_0402_5%  [R_0402]  153.01 55.54 0 bottom
RC79  10K_0402_5%  [R_0402]  151.7 54.58 90 top
RC80  8.2K_0402_5%  [R_0402]  165.15 84.31 180 top
RC81  10K_0402_5%  [R_0402]  158.52 68.62 180 top
RC82  10K_0402_5%  [R_0402]  159.52 69.63 180 top
RC87  0_0402_5%  [R0402_0OHM]  171.59 80.25 180 top
RC88  0_0402_5%  [R0402_0OHM]  171.59 79.29 180 top
RC89  0_0402_5%  [R0402_0OHM]  171.59 82.15 180 top
RC91  47K_0402_5%  [R_0402]  148.48 56.18 180 top
RC92  10K_0402_5%  [R_0402]  155.55 54.58 90 top
RC95  8.2K_0402_5%  [R_0402]  166.01 85.1 270 top
RC98  0_0402_5%  [R_0402]  68.21 57.96 180 bottom
RC99  0_0402_5%  [R_0402]  68.2 55.79 180 bottom
RC102  1K_0402_5%  [R_0402]  59.68 60.76 270 top
RC103  1K_0402_5%  [R_0402]  57.85 58.47 90 top
RC106  1K_0402_5%  [R_0402]  72.23 55.66 90 top
RC109  0_0402_5%  [R_0402]  61.15 57.21 270 bottom
RC112  0_0402_5%  [R_0402]  67.3 59.86 0 bottom
RC113  1K_0402_5%  [R_0402]  69.9 52.5 270 top
RC114  49.9_0402_1%  [R_0402]  108.19 78.53 0 bottom
RC115  0_0402_5%  [R_0402]  67.3 58.91 0 bottom
RC116  62_0402_5%  [R_0402]  106.25 78.24 180 bottom
RC117  51_0402_5%  [R_0402]  70.99 54.46 180 top
RC118  0_0402_5%  [R_0402]  67.28 56.68 0 bottom
RC119  0_0402_5%  [R_0402]  59.61 54.06 90 top
RC120  1K_0402_5%  [R_0402]  59.63 55.92 180 top
RC121  56_0402_5%  [R_0402]  105.34 79.13 0 bottom
RC122  1K_0402_5%  [R_0402]  70.82 55.93 180 top
RC123  10K_0402_5%  [R_0402]  113.03 87.6 90 top
RC124  51_0402_5%  [R_0402]  108.3 90.14 90 bottom
RC125  51_0402_5%  [R_0402]  108.22 88.84 270 bottom
RC126  51_0402_5%  [R_0402]  107.34 90.14 90 bottom
RC127  51_0402_5%  [R_0402]  107.34 88.84 270 bottom
RC128  51_0402_5%  [R_0402]  59.61 52.22 90 top
RC129  51_0402_5%  [R_0402]  61.15 58.99 270 bottom
RC130  200_0402_1%  [R_0402]  111.51 54.03 270 top
RC131  121_0402_1%  [R_0402]  110.56 54.03 270 top
RC132  100_0402_1%  [R_0402]  109.6 54.03 270 top
RC133  24.9_0402_1%  [R_0402]  138.93 77.83 180 top
RC136  0_0402_5%  [R_0402]  154.67 69.57 0 top
RC139  100K_0402_5%  [R_0402]  148.78 87.75 270 top
RC140  1K_0402_5%  [R_0402]  157.93 75.22 0 top
RC141  100K_0402_5%  [R_0402]  149.72 87.74 270 top
RC142  100K_0402_5%  [R_0402]  147.1 87.08 90 bottom
RC149  3.01K_0402_1%  [R_0402]  134 87.1 180 bottom
RC152  22.6_0402_1%  [R_0402]  141.67 65.84 90 top
RC153  10K_0402_5%  [R_0402]  154.68 55.49 270 top
RC155  100K_0402_5%  [R_0402]  157.55 72.49 0 bottom
RC156  100K_0402_5%  [R_0402]  155.59 76.19 270 top
RC158  100K_0402_5%  [R_0402]  154.46 79.53 180 bottom
RC160  100K_0402_5%  [R_0402]  155.32 79.53 270 bottom
RC161  0_0402_5%  [R0402_0OHM]  110.2 88.82 270 bottom
RC163  10K_0402_5%  [R_0402]  153.53 88.19 270 top
RC164  10K_0402_5%  [R_0402]  154.67 89.52 270 top
RC171  10K_0402_5%  [R_0402]  156.68 72.49 180 bottom
RC174  100K_0402_5%  [R_0402]  160.05 67.54 180 top
RC175  100K_0402_5%  [R_0402]  157.29 67.54 0 top
RC176  1K_0402_5%  [R_0402]  151.5 88.19 270 top
RC178  49.9_0402_1%  [R_0402]  144.26 56.44 270 bottom
RC179  1K_0402_5%  [R_0402]  159.03 70.98 90 top
RC180  1K_0402_5%  [R_0402]  158.17 72.61 180 top
RC183  1K_0402_1%  [R_0402]  108.85 70.15 180 bottom
RC184  1K_0402_1%  [R_0402]  108.85 71.04 180 bottom
RC185  49.9_0402_1%  [R_0402]  107.94 66.78 0 bottom
RC186  8.2K_0402_1%  [R_0402]  141.08 88.06 270 bottom
RC187  49.9_0402_1%  [R_0402]  143.37 56.44 270 bottom
RC188  1K_0402_1%  [R_0402]  108.85 71.93 180 bottom
RC189  1K_0402_1%  [R_0402]  108.85 73.71 180 bottom
RC190  1K_0402_1%  [R_0402]  108.85 72.82 180 bottom
RC191  1K_0402_5%  [R_0402]  102.71 55.09 180 top
RC192  0_0402_5%  [R_0402]  150.1 87.08 90 bottom
RC193  0_0402_5%  [R_0402]  110.95 86.85 180 bottom
RC194  0_0402_5%  [R_0402]  157.61 56.49 180 bottom
RC195  0_0402_5%  [R_0402]  110.02 55.47 0 bottom
RC196  0_0603_5%  [R_0603]  112.27 87.99 90 bottom
RC197  150_0402_5%  [R_0402]  109.73 88.49 180 top
RC198  10K_0402_5%  [R_0402]  107.71 88.48 180 top
RC199  10K_0402_5%  [R_0402]  111 90.61 270 bottom
RC201  1.5K_0402_5%  [R_0402]  111.1 88.83 270 bottom
RC202  1K_0402_5%  [R_0402]  117.89 88.24 0 top
RC204  75_0402_1%  [R_0402]  107.32 77.15 270 bottom
RC207  43_0402_5%  [R_0402]  108.26 75.34 90 bottom
RC208  110_0402_1%  [R_0402]  108.19 77.13 0 bottom
RC209  100_0402_1%  [R_0402]  111.27 87.61 180 top
RC211  5.11_0402_1%  [R_0402]  139.32 53.12 90 top
RC212  0_0402_5%  [R0402_0OHM]  152.66 54.58 90 top
RC213  0_0402_5%  [R_0402]  153.8 54.58 90 top
RC216  0_0402_5%  [R_0402]  154.55 52.69 0 top
RC217  0_0402_5%  [R0402_0OHM]  154.55 53.64 0 top
RC218  100_0402_1%  [R_0402]  109.49 87.61 180 top
RC219  0_0402_5%  [R0402_0OHM]  171.59 81.2 180 top
RC224  0_0402_5%  [R0402_0OHM]  173.93 70.46 180 bottom
RC225  0_0402_5%  [R0402_0OHM]  173.93 71.35 180 bottom
RC226  0_0402_5%  [R0402_0OHM]  173.93 72.24 180 bottom
RC227  0_0402_5%  [R0402_0OHM]  173.93 73.13 180 bottom
RC228  0_0402_5%  [R0402_0OHM]  173.93 74.02 180 bottom
RC229  0_0402_5%  [R0402_0OHM]  173.93 75.03 180 bottom
RC230  0_0402_5%  [R0402_0OHM]  173.93 75.92 180 bottom
RC231  0_0402_5%  [R0402_0OHM]  173.01 76.81 0 bottom
RC240  10K_0402_5%  [R_0402]  129.89 87.1 180 bottom
RC241  10K_0402_5%  [R_0402]  130.81 87.1 0 bottom
RC242  10K_0402_5%  [R_0402]  146.24 56.26 270 top
RC243  10K_0402_5%  [R_0402]  145.29 56.26 270 top
RC245  100K_0402_5%  [R_0402]  150.82 55.49 270 top
RC247  10K_0402_5%  [R_0402]  155.82 75.46 270 bottom
RC300  10K_0402_5%  [R_0402]  157 70.51 0 top
RC301  0_0402_5%  [R0402_0OHM]  188.52 72.36 270 bottom
RC302  10K_0402_5%  [R_0402]  163.37 70.75 0 top
RC303  10K_0402_5%  [R_0402]  163.37 71.64 0 top
RC304  100K_0402_5%  [R_0402]  170.56 84.81 180 top
RC305  1K_0402_5%  [R_0402]  64.69 64.59 90 bottom
RD2  470_0402_5%  [R_0402]  76.47 22.45 180 top
RD3  0_0402_5%  [R0402_0OHM]  74.65 23.41 0 top
RD4  1.8K_0402_1%  [R_0402]  63.31 33.7 180 top
RD5  2_0402_1%  [R_0402]  62.4 34.65 0 top
RD6  1.8K_0402_1%  [R_0402]  61.47 35.6 180 top
RD7  24.9_0402_1%  [R_0402]  62.4 36.55 0 top
RD9  220K_0402_5%  [R_0402]  121.27 32.18 270 top
RD10  66.5_0402_1%  [R_0402]  97.48 19.92 180 top
RD11  66.5_0402_1%  [R_0402]  97.48 19.03 180 top
RD12  66.5_0402_1%  [R_0402]  176.34 17.94 180 top
RD13  66.5_0402_1%  [R_0402]  176.34 17.06 180 top
RD14  2M_0402_5%  [R_0402]  121.27 29.49 90 top
RD15  0_0402_5%  [R0402_0OHM]  119.18 25.9 270 top
RD16  0_0402_5%  [R0402_0OHM]  118.23 25.9 270 top
RD18  1.8K_0402_1%  [R_0402]  175.21 22.58 0 top
RD19  2_0402_1%  [R_0402]  177.05 22.58 0 top
RD20  1.8K_0402_1%  [R_0402]  176.86 21.69 0 top
RD21  24.9_0402_1%  [R_0402]  180 21.63 180 top
RD22  1.8K_0402_1%  [R_0402]  134.99 27.72 180 top
RD23  2_0402_1%  [R_0402]  133.08 27.72 180 top
RD24  1.8K_0402_1%  [R_0402]  134.07 26.77 0 top
RD25  24.9_0402_1%  [R_0402]  133.08 25.81 180 top
RD27  0_0402_5%  [R0402_0OHM]  199.44 25.74 90 top
RD28  0_0402_5%  [R0402_0OHM]  198.81 28.79 90 top
RE5  100K_0402_5%  [R_0402]  220.51 45.06 0 top
RE8  100K_0402_5%  [R_0402]  233.21 56.17 0 top
RE9  100K_0402_5%  [R_0402]  237.74 46.17 180 top
RE10  100K_0402_5%  [R_0402]  237.74 47.12 180 top
RE11  100K_0402_5%  [R_0402]  227.32 57.33 270 top
RE12  100K_0402_5%  [R_0402]  226.17 40.44 90 top
RE17  100K_0402_5%  [R_0402]  220.51 45.98 0 top
RE20  100K_0402_5%  [R_0402]  227.06 40.44 90 top
RE21  10K_0402_5%  [R_0402]  233.41 40.57 90 top
RE24  10K_0402_5%  [R_0402]  221.42 53.5 180 top
RE25  100K_0402_5%  [R_0402]  237.74 44.2 180 top
RE26  10_0402_5%  [R_0402]  237.74 43.25 180 top
RE27  33_0402_5%  [R_0402]  221.42 47.89 180 top
RE31  100K_0402_5%  [R_0402]  251.56 72.57 270 top
RE32  0_0402_5%  [R0402_0OHM]  252.51 71.62 270 top
RE33  10K_0402_5%  [R_0402]  250.67 71.66 90 top
RE35  10K_0402_5%  [R_0402]  228.21 57.33 270 top
RE36  100K_0402_5%  [R_0402]  240.77 74.1 270 top
RE37  2.2K_0402_5%  [R_0402]  250.75 61.26 180 top
RE42  10K_0402_5%  [R_0402]  249.77 69.83 0 top
RE43  2.2K_0402_5%  [R_0402]  250.75 62.15 180 top
RE48  10K_0402_5%  [R_0402]  233.39 63.86 0 top
RE51  10K_0402_5%  [R_0402]  231.95 64.91 90 top
RE55  100K_0402_5%  [R_0402]  233.39 62.91 0 top
RE56  10K_0402_5%  [R_0402]  239.5 53.56 90 top
RE57  1K_0402_5%  [R_0402]  253.07 64.05 0 top
RE58  100K_0402_5%  [R_0402]  252.13 64.07 270 top
RE60  43_0402_5%  [R_0402]  246.99 55.68 270 top
RE61  0_0402_5%  [R0402_0OHM]  249.78 67.62 270 top
RE62  100K_0402_5%  [R_0402]  250.68 70.72 180 top
RE63  100K_0402_5%  [R_0402]  247.05 52.13 270 top
RE64  4.7K_0402_5%  [R_0402]  253.07 63.1 0 top
RE65  100_0402_1%  [R_0402]  244.77 51.21 90 top
RE66  10_0402_5%  [R_0402]  234.3 60.05 180 top
RE67  10K_0402_5%  [R_0402]  233.03 71.27 270 top
RE68  100K_0402_5%  [R_0402]  231.43 69.34 270 top
RE69  8.2K_0402_5%  [R_0402]  233.41 57.49 90 top
RE70  2.2K_0402_5%  [R_0402]  229.27 61.06 0 top
RE71  49.9_0402_1%  [R_0402]  254.5 51.49 270 top
RE72  10K_0402_5%  [R_0402]  250.75 52.12 270 top
RE73  10K_0402_5%  [R_0402]  248.84 52.12 270 top
RE74  10K_0402_5%  [R_0402]  247.96 52.12 270 top
RE75  100K_0402_5%  [R_0402]  249.8 52.12 270 top
RE77  1.58K_0402_1%  [R_0402]  234.3 65.77 180 top
RE78  1K_0402_5%  [R_0402]  234.3 61.01 180 top
RE79  33K_0402_5%  [R_0402]  241.72 74.1 270 top
RE81  10K_0402_5%  [R_0402]  254.35 69.84 270 top
RE82  10K_0402_5%  [R_0402]  253.47 69.84 270 top
RE83  100K_0402_5%  [R_0402]  240.28 45.28 180 top
RE85  100K_0402_5%  [R_0402]  240.28 47.12 180 top
RE86  10K_0402_5%  [R_0402]  246.91 49.87 0 top
RE87  100K_0402_5%  [R_0402]  240.28 46.24 180 top
RE88  47K_0402_5%  [R_0402]  242.91 56.16 270 top
RE274  0_0402_5%  [R_0402]  230 57.25 180 top
RE275  0_0402_5%  [R0402_0OHM]  229.08 56.36 0 top
RE276  10K_0402_5%  [R_0402]  225.23 40.44 90 top
RE277  100K_0402_5%  [R_0402]  231.06 65.9 270 top
RE279  0_0402_5%  [R0402_0OHM]  233.95 71.27 270 top
RE280  0_0402_5%  [R_0402]  238.01 55.9 270 top
RE281  0_0402_5%  [R_0402]  232.42 72.16 0 top
RE282  0_0402_5%  [R0402_0OHM]  234.18 72.16 0 top
RE283  0_0402_5%  [R_0402]  247.64 70.36 90 top
RE284  2.2K_0402_5%  [R_0402]  229.02 68.8 270 top
RI13  10K_0402_5%  [R_0402]  77.46 91.43 270 top
RI14  22.1K_0402_1%  [R_0402]  80.94 95.24 180 top
RL1  10K_0402_5%  [R_0402]  243.51 89.07 180 top
RL2  10K_0402_5%  [R_0402]  243.51 90.86 180 top
RL3  0_0402_5%  [R0402_0OHM]  230.99 90.18 0 top
RL4  4.7K_0402_5%  [R_0402]  234.68 92.93 90 top
RL5  10K_0402_5%  [R_0402]  232.7 94.45 270 top
RL6  4.7K_0402_5%  [R_0402]  233.79 93.84 270 top
RL7  0_0402_5%  [R0402_0OHM]  230.91 94.46 270 top
RL8  0_0603_5%  [R0603_0OHM]  230.84 92.51 0 top
RL9  10K_0402_5%  [R_0402]  231.8 93.54 90 top
RL10  0_0402_5%  [R0402_0OHM]  230.61 86.02 0 top
RL11  1M_0402_5%  [R_0402]  232.4 86.03 270 top
RL12  1K_0402_5%  [R_0402]  242.77 87.3 0 top
RL13  3.01K_0402_1%  [R_0402]  233.29 83.36 270 top
RL14  150_0402_5%  [R_0402]  260.59 86.96 90 top
RL15  75_0402_1%  [R_0402]  248.91 93.46 270 top
RL16  75_0402_1%  [R_0402]  250.18 93.46 270 top
RL17  75_0402_1%  [R_0402]  256.53 93.4 270 top
RL18  75_0402_1%  [R_0402]  257.8 93.4 270 top
RL19  150_0402_5%  [R_0402]  261.48 86.96 90 top
RL20  150_0402_5%  [R_0402]  262.37 86.96 90 top
RL29  1M_0402_5%  [R_0402]  259.83 77.7 90 top
RL30  1M_0402_5%  [R_0402]  261.44 76.3 0 top
RN1  10K_0402_5%  [R_0402]  40.45 11.4 180 top
RN3  2.2K_0402_5%  [R_0402]  173.29 62.22 270 top
RN4  2.2K_0402_5%  [R_0402]  174.17 62.22 270 top
RN6  10K_0402_5%  [R_0402]  38.65 25.03 90 top
RN7  10K_0402_5%  [R_0402]  39.54 25.95 270 top
RPC1  10K_8P4R_5%  [RP_0804_8P4R]  156.67 53.93 90 top
RPC2  2.2K_0804_8P4R_5%  [RP_0804_8P4R]  145.07 87.54 90 bottom
RPC3  10K_8P4R_5%  [RP_0804_8P4R]  160.58 78 0 top
RPC4  10K_8P4R_5%  [RP_0804_8P4R]  158.39 76.5 180 top
RPC5  10K_8P4R_5%  [RP_0804_8P4R]  165.22 64.31 180 top
RPC6  10K_8P4R_5%  [RP_0804_8P4R]  160.58 73.65 0 bottom
RPC7  10K_8P4R_5%  [RP_0804_8P4R]  165.22 66.32 180 bottom
RPC8  10K_8P4R_5%  [RP_0804_8P4R]  161.73 78 180 bottom
RPC9  10K_8P4R_5%  [RP_0804_8P4R]  161.73 73.65 180 top
RPC10  10K_8P4R_5%  [RP_0804_8P4R]  165.22 61.26 180 top
RPC11  33_0804_8P4R_5%  [RP_0804_8P4R]  164.13 72.88 0 bottom
RPC12  33_0804_8P4R_5%  [RP_0804_8P4R]  164.13 74.38 0 top
RPC14  2.2K_0804_8P4R_5%  [RP_0804_8P4R]  164.13 69.96 0 bottom
RPC15  10K_8P4R_5%  [RP_0804_8P4R]  160.77 71.84 0 top
RPC16  10K_8P4R_5%  [RP_0804_8P4R]  165.22 76.95 180 top
RPC17  10K_8P4R_5%  [RP_0804_8P4R]  158.38 77.95 180 bottom
RPC18  10K_8P4R_5%  [RP_0804_8P4R]  158.38 75.15 180 bottom
RPC19  10K_8P4R_5%  [RP_0804_8P4R]  158.06 67.74 0 bottom
RPC20  100K_0804_8P4R_5%  [RP_0804_8P4R]  149.52 89.25 90 bottom
RPC21  51_0804_8P4R_5%  [RP_0804_8P4R]  97.97 55.8 180 top
RPE2  4.7K_8P4R_5%  [RP_0804_8P4R]  240.71 51.67 90 top
RPE3  2.2K_0804_8P4R_5%  [RP_0804_8P4R]  243.32 72.62 90 top
RPE4  100K_0804_8P4R_5%  [RP_0804_8P4R]  221.48 54.79 180 top
RPE5  100K_0804_8P4R_5%  [RP_0804_8P4R]  246.24 72.62 90 top
RPE6  10K_8P4R_5%  [RP_0804_8P4R]  245.71 55.04 270 top
RPE7  10K_8P4R_5%  [RP_0804_8P4R]  251.9 50.52 90 top
RPE8  100K_0804_8P4R_5%  [RP_0804_8P4R]  221.35 49.77 180 top
RPE9  100K_0804_8P4R_5%  [RP_0804_8P4R]  229.84 41.1 270 top
RPE10  100K_0804_8P4R_5%  [RP_0804_8P4R]  236.78 73.07 90 top
RPV1  2.2K_0804_8P4R_5%  [RP_0804_8P4R]  187.73 84.82 180 top
RPV2  2.2K_0804_8P4R_5%  [RP_0804_8P4R]  197.71 73.7 270 top
RR1  10_0402_5%  [R_0402]  259.75 22.19 90 top
RR2  191_0402_1%  [R_0402]  253.89 19.46 0 top
RR3  0_0402_5%  [R0402_0OHM]  258.86 22.19 90 top
RR4  0_0402_5%  [R0402_0OHM]  257.97 22.19 90 top
RR5  4.7K_0402_1%  [R_0402]  265.96 13.57 0 top
RR6  100K_0402_5%  [R_0402]  259.18 10.95 90 top
RR8  100K_0402_5%  [R_0402]  260.07 11.87 270 top
RR11  1M_0402_5%  [R_0402]  261.73 9.64 270 top
RR15  10K_0402_5%  [R_0402]  255.38 10.91 270 top
RV1  4.7K_0402_5%  [R_0402]  59.5 75.6 180 top
RV2  4.7K_0402_5%  [R_0402]  63.18 75.6 180 top
RV3  100K_0402_5%  [R_0402]  48.77 69.57 270 top
RV4  270K_0402_5%  [R_0402]  61.46 65 0 bottom
RV5  47K_0402_5%  [R_0402]  63.31 65.91 270 bottom
RV6  10K_0402_5%  [R_0402]  76.7 80.44 270 top
RV7  2.2K_0402_5%  [R_0402]  221.6 97.71 270 top
RV8  10K_0402_5%  [R_0402]  223.32 95.87 270 top
RV9  2.2K_0402_5%  [R_0402]  220.71 97.71 270 top
RV14  2.2K_0402_5%  [R_0402]  184.32 86.33 0 top
RV50  4.99K_0402_1%  [R_0402]  212.36 85.01 180 top
RV51  4.7K_0402_5%  [R_0402]  225.58 82.84 180 top
RV52  4.7K_0402_5%  [R_0402]  224.67 81.89 0 top
RV54  4.7K_0402_5%  [R_0402]  213.49 81.85 270 top
RV55  4.7K_0402_5%  [R_0402]  212.38 83.1 180 top
RV56  4.7K_0402_5%  [R_0402]  212.38 82.22 180 top
RV57  4.7K_0402_5%  [R_0402]  225.58 87.79 180 top
RV58  4.7K_0402_5%  [R_0402]  224.86 93.13 0 top
RV60  4.7K_0402_5%  [R_0402]  223.48 93.59 270 top
RV61  4.7K_0402_5%  [R_0402]  214.38 80.93 90 top
RV62  4.7K_0402_5%  [R_0402]  215.19 87.32 90 bottom
RV63  4.7K_0402_5%  [R_0402]  224.67 88.68 0 top
RV64  4.7K_0402_5%  [R_0402]  215.19 90.02 270 bottom
RV65  4.7K_0402_5%  [R_0402]  225.77 94.02 180 top
RV66  4.7K_0402_5%  [R_0402]  222.59 92.67 90 top
RV67  1M_0402_5%  [R_0402]  225.58 80.94 180 top
RV68  100K_0402_5%  [R_0402]  216.43 92.38 0 bottom
RV73  1M_0402_5%  [R_0402]  197.35 88.89 270 top
RV74  1M_0402_5%  [R_0402]  189.92 74.41 270 top
RV75  1M_0402_5%  [R_0402]  188.05 82.62 90 top
RV76  150_0402_1%  [R_0402]  194.23 88.95 270 top
RV77  150_0402_1%  [R_0402]  193.31 88.95 270 top
RV78  150_0402_1%  [R_0402]  192.39 88.95 270 top
RV79  100K_0402_5%  [R_0402]  203.4 74.94 270 top
RV80  1M_0402_5%  [R_0402]  201.23 88.05 180 top
RV81  2.2K_0402_5%  [R_0402]  199.25 88.87 270 top
RV82  1M_0402_5%  [R_0402]  188.06 81.75 180 top
RV83  2.2K_0402_5%  [R_0402]  203.28 76.79 0 top
RV84  1M_0402_5%  [R_0402]  205.22 75.6 90 top
RV85  1M_0402_5%  [R_0402]  190.81 74.41 270 top
RV86  10K_0402_5%  [R_0402]  202.95 71.54 180 bottom
RV87  2.2K_0402_5%  [R_0402]  207.89 73.24 90 bottom
RV88  10K_0402_5%  [R_0402]  198.3 88.87 270 top
RV89  3.74K_0402_1%  [R_0402]  196.2 87.97 90 top
RV90  100K_0402_5%  [R_0402]  185.23 85.45 180 top
RV91  100K_0402_5%  [R_0402]  187.26 77.57 180 top
RV100  4.7K_0402_5%  [R_0402]  226.51 80.05 0 top
RV501  100K_0402_5%  [R_0402]  261.1 75.17 270 top
RV502  100K_0402_5%  [R_0402]  260.15 75.17 270 top
RV503  5.1M_0402_5%  [R_0402]  271.26 82.96 90 top
RV504  1M_0402_5%  [R_0402]  268.72 71.84 90 top
RV505  100K_0402_5%  [R_0402]  267.84 75.03 180 top
RV507  100K_0402_5%  [R_0402]  267.84 74.02 180 top
RV508  1M_0402_5%  [R_0402]  188.14 83.65 90 bottom
RV509  1M_0402_5%  [R_0402]  187.27 74.94 90 top
RV516  2.2K_0402_5%  [R_0402]  204.27 74.94 270 top
RV517  2.2K_0402_5%  [R_0402]  205.22 73.84 90 top
RV518  2.2K_0402_5%  [R_0402]  186.35 79.35 0 top
RV519  2.2K_0402_5%  [R_0402]  186.35 78.46 0 top
RV550  4.7K_0402_5%  [R_0402]  224.67 84.81 0 top
RV551  4.7K_0402_5%  [R_0402]  225.58 83.86 180 top
RV554  100K_0402_5%  [R_0402]  225.58 90.46 180 top
RV555  100K_0402_5%  [R_0402]  225.58 89.57 180 top
RV600  4.99K_0402_1%  [R_0402]  212.38 79.29 180 top
RV601  4.7K_0402_5%  [R_0402]  227.43 78.21 180 top
RV602  4.7K_0402_5%  [R_0402]  211.46 80.17 0 top
RV603  4.7K_0402_5%  [R_0402]  227.43 80.94 180 top
RV604  100K_0402_5%  [R_0402]  212.36 72.99 90 top
RV605  100K_0402_5%  [R_0402]  211.4 75.67 0 top
RV606  1M_0402_5%  [R_0402]  228.22 72.73 180 top
RV607  1M_0402_5%  [R_0402]  211.59 71.16 0 top
RV608  100K_0402_5%  [R_0402]  211.4 74.78 0 top
RV609  100K_0402_5%  [R_0402]  211.4 76.56 0 top
RV610  4.7K_0402_5%  [R_0402]  228.35 79.1 0 top
RV611  4.7K_0402_5%  [R_0402]  226.52 74.07 90 top
RV612  4.7K_0402_5%  [R_0402]  229.19 74.07 90 top
RV613  4.7K_0402_5%  [R_0402]  229.19 77.01 270 top
RV614  4.7K_0402_5%  [R_0402]  226.52 77.01 270 top
RV615  4.7K_0402_5%  [R_0402]  227.43 79.1 180 top
RV616  4.7K_0402_5%  [R_0402]  229.27 79.98 180 top
RV617  4.7K_0402_5%  [R_0402]  227.41 74.98 270 top
RV618  4.7K_0402_5%  [R_0402]  228.3 74.98 270 top
RV619  4.7K_0402_5%  [R_0402]  228.3 76.1 90 top
RV620  4.7K_0402_5%  [R_0402]  227.41 76.1 90 top
RV701  100K_0402_5%  [R_0402]  189.33 71.34 0 top
RV702  10_0402_5%  [R_0402]  195.02 72.2 180 top
RZ5  100K_0402_5%  [R_0402]  138.29 94.4 270 top
RZ8  2.2K_0402_5%  [R_0402]  242.02 14.27 270 top
RZ9  2.2K_0402_5%  [R_0402]  242.91 14.27 270 top
RZ10  1M_0402_5%  [R_0402]  248.21 14.27 270 top
RZ14  100K_0402_5%  [R_0402]  211.63 17.36 90 top
RZ15  100K_0402_5%  [R_0402]  211.63 20.05 270 top
RZ16  100K_0402_5%  [R_0402]  134.31 93 90 top
RZ17  0_0402_5%  [R0402_0OHM]  189.46 52.76 270 top
RZ18  4.7K_0402_5%  [R_0402]  219.52 17.04 180 top
RZ19  4.7K_0402_5%  [R_0402]  216.83 17.04 0 top
RZ21  33_0402_5%  [R_0402]  254.37 58.15 180 top
RZ22  10K_0402_5%  [R_0402]  251.4 55.66 180 top
RZ24  10K_0402_5%  [R_0402]  213.93 91.1 180 bottom
RZ25  330_0402_5%  [R_0402]  205.92 94.7 90 top
RZ26  33_0402_5%  [R_0402]  191.3 52.76 270 top
RZ27  680_0402_5%  [R_0402]  207.28 86.88 270 bottom
RZ28  330_0402_5%  [R_0402]  203.89 96.94 90 top
RZ29  33_0402_5%  [R_0402]  188.57 52.76 270 top
RZ30  33_0402_5%  [R_0402]  186.66 52.76 270 top
RZ31  100K_0402_5%  [R_0402]  265.23 83.04 270 bottom
RZ32  220_0402_5%  [R_0402]  268.08 87.43 270 top
RZ33  330_0402_5%  [R_0402]  261.73 82.57 90 top
RZ34  680_0402_5%  [R_0402]  262.99 84.35 0 bottom
RZ35  33_0402_5%  [R_0402]  190.41 52.76 270 top
RZ36  220_0402_5%  [R_0402]  206.74 88.7 180 bottom
RZ37  100K_0402_5%  [R_0402]  222.59 57.56 90 top
RZ38  100K_0402_5%  [R_0402]  237.74 52.55 180 top
RZ39  10K_0402_5%  [R_0402]  226.16 60.86 0 top
RZ40  100K_0402_5%  [R_0402]  207.12 45.43 90 top
RZ41  0_0402_5%  [R_0402]  193.75 54.61 0 top
RZ42  0_0402_5%  [R0402_0OHM]  194.67 55.64 180 top
RZ43  1K_0402_5%  [R_0402]  205.92 96.54 90 top
RZ44  390_0402_5%  [R_0402]  202.55 94.64 90 top
RZ45  0_0603_5%  [R_0603]  58.09 72.94 180 top
RZ46  0_0603_5%  [R_0603]  62.41 77.25 0 top
RZ47  0_0603_5%  [R_0603]  65.14 78.27 0 top
RZ48  0_0603_5%  [R_0603]  67.55 79.35 0 top
RZ50  0_0402_5%  [R0402_0OHM]  225.46 59.97 0 top
RZ51  0_0402_5%  [R0402_0OHM]  256.74 57.28 0 top
RZ52  0.01_1206_1%  [R_1206]  180.07 49.39 180 top
RZ53  0_0603_5%  [R0603_0OHM]  178.04 51.03 0 top
RZ54  0_0603_5%  [R_0603]  205.5 43.79 180 top
RZ55  0_0603_5%  [R0603_0OHM]  202.69 42.07 0 top
RZ56  0_0402_5%  [R_0402]  221.39 36.54 270 top
RZ57  0_0402_5%  [R0402_0OHM]  220.43 36.54 270 top
ST1  -  [CLIP_C5P1]  77.2 80.1 180 bottom
ST2  -  [H_3P3]  181.85 65.15 0 top
ST3  -  [H_3P3]  68.21 45.52 0 top
SW1  SS3-CMFTQR9_3P  [SW_SS3-CMFTQR9_3P]  186.05 69.24 90 bottom
SW2  SKRBAAE010_4P  [SW_SKRBAAE010_4P]  278.74 89.2 90 top
T8  PAD~D  [TPC12]  148.7 60.11 0 top
T9  PAD~D  [TPC12]  147.35 67.96 0 top
T10  PAD~D  [TPC12]  105.72 87.96 180 bottom
T11  PAD~D  [TPC12]  109.29 79.41 180 bottom
T12  PAD~D  [TPC12]  115.35 87.07 0 top
T13  PAD~D  [TPC12]  106.63 86.92 180 bottom
T14  PAD~D  [TPC12]  113.94 86.66 0 top
T15  PAD~D  [TPC12]  113.98 85.09 0 top
T16  PAD~D  [TPC12]  149.05 68.73 0 top
T21  PAD~D  [TPC12]  149.4 67.06 0 top
T22  PAD~D  [TPC12]  156.07 72.05 0 top
T27  PAD~D  [TPC12]  156.17 67.5 180 bottom
T28  PAD~D  [TPC12]  108.99 55.77 180 bottom
T29  PAD~D  [TPC12]  107.94 56.87 180 bottom
